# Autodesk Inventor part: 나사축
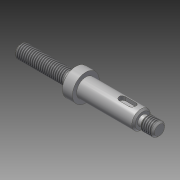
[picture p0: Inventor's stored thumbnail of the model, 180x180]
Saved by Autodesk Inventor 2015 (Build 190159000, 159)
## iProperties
Created: 2019-10
Part Number: 나사축
Material: 강철, 연강
Document SubType Name: Modeling
Designer: mduedu
Density: 1 g/cm^3
Appearance: 강철
Author: mduedu
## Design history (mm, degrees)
revolve "회전1" stored, may be unused: angle "d9" = 90 deg
sketch "스케치2"
  geometry: L1 (0, 4)-(0, -4) reference; L2 (0, -4)-(-33, -4) reference; L3 (-33, -4)-(-33, -8) reference; L4 (-33, -8)-(-39, -8) reference; L5 (-39, -8)-(-39, -5.5) reference; L6 (-39, -5.5)-(-73, -5.5) reference; L7 (-73, -5.5)-(-73, -3) reference; L8 (-76, -4)-(-83, -4) reference; L9 (-83, -4)-(-83, 4) reference; L10 (-83, 4)-(-76, 4) reference; L11 (-73, 3)-(-73, 5.5) reference; L12 (-73, 5.5)-(-39, 5.5) reference; L13 (-39, 5.5)-(-39, 8) reference; L14 (-39, 8)-(-33, 8) reference; L15 (-33, 8)-(-33, 4) reference; L16 (-33, 4)-(0, 4) reference; L17 (0, 0)-(-83, 0); L18 (-31, 3)-(-33, 3); L19 (-33, 3)-(-33, 4); L20 (-31, 3)-(-29.268, 4); L21 (-33, 4)-(-29.268, 4); L22 (-73, -3)-(-75, -3) reference; L23 (-75, -3)-(-76, -4) reference; L24 (-76, 4)-(-75, 3) reference; L25 (-75, 3)-(-73, 3) reference
  constraints: 10 end point, 1 collinear, 1 midpoint, 1 point on line, 1 vertical
  dimensions: "d13" = 1 distance between parallel lines of L18 L21; "d15" = 30 deg angle of L16 L20; "d17" = 2 distance of L18.start L18.end
revolve "회전2" sketch "스케치2" stored, may be unused: angle "d12" = 90 deg
feature "스레드1" dims "d18" = 10, "d19" = 0
feature "스레드2" dims "d20" = 7, "d21" = 0
chamfer "모따기1" distance "d22" = 1; stored, may be unused: second distance "d23" = 2, angle "d24" = 30 deg
chamfer "모따기2" distance "d25" = 1; stored, may be unused: second distance "d26" = 2, angle "d27" = 30 deg
sketch "스케치3"
  geometry: L1 (-31, -3)-(-33, -3) reference; L2 (-33, -3)-(-33, -8) reference; L3 (-33, -8)-(-39, -8) reference; L4 (-39, -8)-(-39, -5.5) reference; L5 (-39, -5.5)-(-72, -5.5) reference; L6 (-72, -5.5)-(-73, -4.5) reference; L7 (-73, -4.5)-(-73, -3) reference; L8 (-76, -4)-(-82, -4) reference; L9 (-82, -4)-(-83, -3) reference; L10 (-83, -3)-(-83, 3) reference; L11 (-83, 3)-(-82, 4) reference; L12 (-82, 4)-(-76, 4) reference; L13 (-73, 3)-(-73, 4.5) reference; L14 (-73, 4.5)-(-72, 5.5) reference; L15 (-72, 5.5)-(-39, 5.5) reference; L16 (-39, 5.5)-(-39, 8) reference; L17 (-39, 8)-(-33, 8) reference; L18 (-33, 8)-(-33, 3) reference; L19 (-33, 3)-(-31, 3) reference; L20 (-31, 3)-(-29.268, 4) reference; L21 (-29.268, 4)-(-1, 4) reference; L22 (-1, 4)-(0, 3) reference; L23 (0, 3)-(0, -3) reference; L24 (0, -3)-(-1, -4) reference; L25 (-1, -4)-(-29.268, -4) reference; L26 (-29.268, -4)-(-31, -3) reference; L27 (-59, 5.5)-(-69, 5.5); L28 (-69, 5.5)-(-69, 3); L29 (-69, 3)-(-59, 3); L30 (-59, 3)-(-59, 5.5); L31 (-73, -3)-(-75, -3) reference; L32 (-75, -3)-(-76, -4) reference; L33 (-76, 4)-(-75, 3) reference; L34 (-75, 3)-(-73, 3) reference; 1 further point
  constraints: 8 end point, 2 parallel, 1 horizontal, 1 perpendicular, 1 point on line
  dimensions: "d28" = 20 distance between parallel lines of L30 L16; "d29" = 10 distance of L27.start L27.end; "d30" = 2.5 distance of L27.end L28.end
extrude "돌출1" cut sketch "스케치3" stored distance "d31" = 4; taper "d32" = 0 deg
fillet "모깎기1"
fillet "모깎기2"
fillet "모깎기3" dims "d36" = 0.6
node "솔리드1"
sketch "스케치1"
  geometry: L1 (0, 0)-(33, 0); L2 (33, 0)-(33, 4); L3 (33, 4)-(0, 4); L4 (0, 4)-(0, 0); L5 (33, 0)-(39, 0); L6 (39, 0)-(39, 8); L7 (39, 8)-(33, 8); L8 (33, 8)-(33, 0); L9 (39, 0)-(73, 0); L10 (73, 0)-(73, 5.5); L11 (73, 5.5)-(39, 5.5); L12 (39, 5.5)-(39, 0); L13 (73, 0)-(83, 0); L14 (83, 0)-(83, 4); L15 (83, 4)-(76, 4); L16 (73, 4)-(73, 0); L17 (73, 3)-(75, 3); L18 (75, 3)-(76, 4)
  constraints: 36 end point, 8 parallel, 5 perpendicular, 4 horizontal, 1 point on line
  dimensions: "d0" = 83 distance between parallel lines of L14 L4; "d2" = 8 diameter of L15 L13; "d3" = 11 diameter of L11 L9; "d4" = 16 diameter of L7 L5; "d5" = 8 diameter of L3 L1; "d6" = 33 distance of L2.end L3.end; "d7" = 6 distance of L6.end L7.end; "d8" = 40 distance between parallel lines of L10 L8; "d33" = 2 distance of L17.start L17.end; "d34" = 135 deg angle of L18 L17; "d35" = 6 diameter of L17 L13 (computed from d2)
node "절단 모서리 투영1"
node "절단 모서리 투영2"
